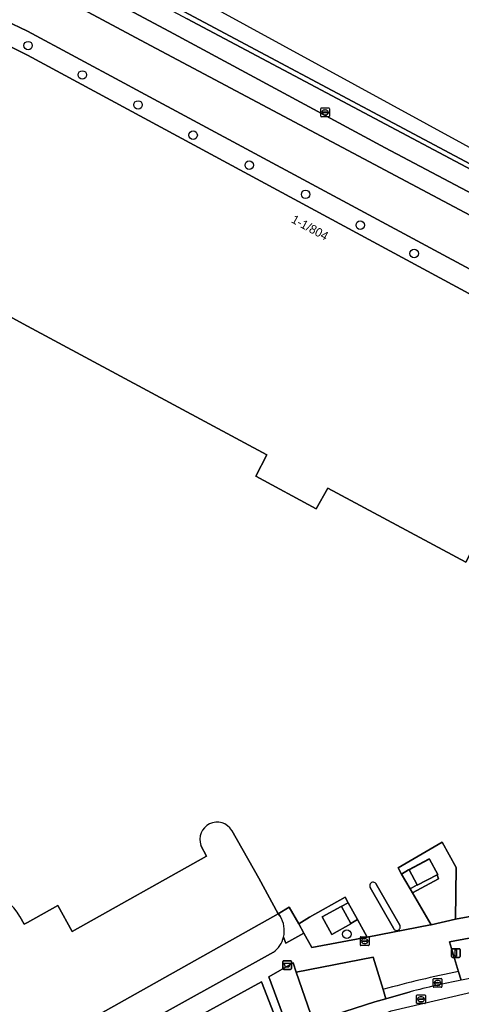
# Model space of a CAD drawing. Extents: x 159262 to 160143, y 383399 to 384319.
# Drawn here: x 159999.1 to 160049.8, y 383753.3 to 383866.4 of the extents above; entities that cross this region are included whole.
import ezdxf

# ---------------------------------------------------------------- set-up
doc = ezdxf.new("R2010")
doc.units = 0
for name, color, linetype in [('IMGEO_Afvalbak', 7, 'Continuous'), ('IMGEO_Berm_gesloten', 7, 'Continuous'), ('IMGEO_Boom', 7, 'Continuous'), ('IMGEO_Erf', 7, 'Continuous'), ('IMGEO_Fietspad_gesloten', 7, 'Continuous'), ('IMGEO_Groenvoorziening', 7, 'Continuous'), ('IMGEO_Kolk', 7, 'Continuous'), ('IMGEO_Lage_trafo', 7, 'Continuous'), ('IMGEO_Lichtmast', 7, 'Continuous'), ('IMGEO_Pand', 7, 'Continuous'), ('IMGEO_Pand_nummerreeks', 7, 'Continuous'), ('IMGEO_Parkeervlak_open', 7, 'Continuous'), ('IMGEO_Rijbaan_lokaal_gesloten', 7, 'Continuous'), ('IMGEO_Rioolput', 7, 'Continuous'), ('IMGEO_Voetpad_onverhard', 7, 'Continuous'), ('IMGEO_Voetpad_open', 7, 'Continuous')]:
    doc.layers.add(name, color=color, linetype=linetype)

msp = doc.modelspace()

# ---------------------------------------------------------------- linework, layer by layer
at = {"layer": 'IMGEO_Afvalbak'}
for p, q in [((160029.32, 383757.41), (160029.32, 383758.21)), ((160029.32, 383758.21), (160029.32, 383757.41)), ((160029.42, 383758.31), (160030.21, 383758.31)), ((160030.21, 383758.31), (160029.42, 383758.31)), ((160030.31, 383758.21), (160030.31, 383757.41)), ((160030.31, 383757.41), (160030.31, 383758.21)), ((160030.21, 383757.31), (160029.42, 383757.31)), ((160029.42, 383757.31), (160030.21, 383757.31))]:
    msp.add_line(p, q, dxfattribs=at)
msp.add_lwpolyline([(160029.46, 383758.03), (160030.17, 383758.03), (160030.02, 383757.56), (160029.61, 383757.56), (160029.46, 383758.03)], dxfattribs=at)
for centre, start, end in [((160029.42, 383758.21), 90, 180), ((160029.42, 383758.21), 90, 180), ((160030.21, 383758.21), 0, 90), ((160030.21, 383758.21), 360, 90), ((160029.42, 383757.41), 180, 270), ((160029.42, 383757.41), 180, 270), ((160030.21, 383757.41), 270, 0), ((160030.21, 383757.41), 270, 0)]:
    msp.add_arc(centre, 0.1, start, end, dxfattribs=at)
at = {"layer": 'IMGEO_Berm_gesloten'}
msp.add_lwpolyline([(159918.59, 383919.81), (159961.28, 383897), (159968.69, 383893.04), (160018.36, 383866.49), (160080.53, 383833.46), (160080.74, 383833.89), (159981.57, 383886.75), (159976.83, 383889.28)], dxfattribs=at)
at = {"layer": 'IMGEO_Boom'}
for centre in [(160000.08, 383863.42), (160006.31, 383860.05), (160012.7, 383856.61), (160019.02, 383853.13), (160025.47, 383849.69), (160031.94, 383846.34), (160038.21, 383842.79), (160044.4, 383839.55), (160036.67, 383761.36)]:
    msp.add_circle(centre, 0.489, dxfattribs=at)
at = {"layer": 'IMGEO_Erf'}
for points in [[(160059.65, 383769.61), (160059.1, 383772.65), (160054.73, 383772.65), (160054.73, 383772.95), (160054.15, 383773), (160054.45, 383777.99), (160054.74, 383782.8), (160052.48, 383783.01), (160053.43, 383787.92), (160055.71, 383799.6), (160057.92, 383798.99), (160058.58, 383801.32), (160050.95, 383805.29), (160050.31, 383804.09), (160034.47, 383812.6), (160033.14, 383810.21), (160026.23, 383813.96), (160027.49, 383816.42), (160000.02, 383831.2), (159992.6, 383835.2)], [(160023.48, 383773.27), (160026.56, 383767.79), (160028.78, 383763.7), (160030.05, 383764.45), (160031.15, 383762.56), (160032.4, 383763.31), (160036.46, 383765.6), (160036.82, 383764.96), (160037.9, 383763.06), (160039.02, 383761.03), (160046.26, 383762.43), (160046.33, 383762.45), (160044.19, 383766.09), (160043.93, 383766.55), (160042.95, 383768.25), (160042.55, 383768.97), (160047.6, 383771.91), (160049.23, 383769.01), (160049.13, 383763.07), (160056.27, 383764.37)], [(160020.56, 383770.33), (160019.91, 383771.54)], [(159999.12, 383763.37), (159999.65, 383762.5), (160000, 383762.7), (160003.48, 383764.65), (160005.15, 383761.68), (160020.56, 383770.33)], [(160042.01, 383762.04), (160039.35, 383766.72)], [(160040.05, 383767.09), (160042.74, 383762.39)]]:
    msp.add_lwpolyline(points, dxfattribs=at)
for centre, radius, start, end in [((160021.78, 383772.24), 1.99, 31.1501, 200.4441), ((160039.69, 383766.93), 0.4, 23.4886, 211.9549), ((159994.53, 383760.99), 5.18, 27.444, 133.522), ((160042.39, 383762.18), 0.406, 201.2941, 29.9981)]:
    msp.add_arc(centre, radius, start, end, dxfattribs=at)
at = {"layer": 'IMGEO_Fietspad_gesloten'}
for points in [[(159896.82, 383934.32), (159893.73, 383935.93), (159892.54, 383933.73), (159890.78, 383934.66), (159879.57, 383940.64), (159878.49, 383938.61), (159961, 383894.56), (159966.3, 383891.73), (160016.32, 383865.03), (160041.05, 383851.68), (160089.35, 383826.13)], [(160089.21, 383828.94), (160080.53, 383833.46), (160018.36, 383866.49)]]:
    msp.add_lwpolyline(points, dxfattribs=at)
at = {"layer": 'IMGEO_Groenvoorziening'}
for points in [[(160013.57, 383863.75), (159997.1, 383872.57), (159994.59, 383867.87), (159997.45, 383866.31), (160000, 383865.1), (160011.11, 383859.11), (160012.51, 383858.36), (160065.36, 383829.9), (160066.69, 383829.19), (160076.7, 383823.82), (160077.15, 383823.18), (160076.02, 383821.25), (160075.79, 383820.82), (160077.91, 383819.68), (160080.61, 383823.12), (160082.68, 383826.22), (160082.91, 383826.85), (160067.94, 383834.83)], [(160049.23, 383769.01), (160047.6, 383771.91), (160042.55, 383768.97), (160042.95, 383768.25), (160043.75, 383768.74), (160046.12, 383770), (160046.13, 383769.97), (160046.15, 383769.98), (160047.1, 383768.22), (160047.03, 383768.18), (160047.2, 383767.73), (160044.19, 383766.09), (160046.33, 383762.45), (160049.13, 383763.07)], [(160033.85, 383763.36), (160036.01, 383764.53), (160036, 383764.55), (160036.82, 383764.96), (160036.46, 383765.6), (160032.4, 383763.31), (160031.15, 383762.56), (160031.74, 383761.49), (160032.67, 383759.81), (160039.02, 383761.03), (160037.9, 383763.06), (160037.12, 383762.57), (160037.14, 383762.53), (160034.93, 383761.34)], [(160039.88, 383753.6), (160041.14, 383753.95), (160040.82, 383755), (160039.7, 383758.71), (160030.87, 383756.98), (160032.85, 383751.24), (160033.04, 383751.31), (160033.1, 383751.33), (160033.49, 383751.47), (160035.26, 383752.11)]]:
    msp.add_lwpolyline(points, close=True, dxfattribs=at)
for points in [[(160029, 383763.42), (160028.78, 383763.7), (160007.73, 383751.86), (160007.88, 383751.56)], [(160056.35, 383759.21), (160056.19, 383759.42), (160055.82, 383761.85), (160048.46, 383760.47), (160049.5, 383757.05), (160049.81, 383756.06)], [(160011.49, 383750), (160028.25, 383759.29)], [(160030.87, 383756.98), (160030.51, 383758.05), (160027.7, 383756.47), (160029.29, 383752.2), (160029.23, 383751.91)], [(160030.33, 383750.3), (160030.39, 383750.31), (160030.41, 383750.32), (160032.85, 383751.24), (160030.87, 383756.98)], [(160026.88, 383755.88), (160019.77, 383751.96), (160019.95, 383751.6), (160021.1, 383749.24)], [(160028.28, 383752.25), (160026.88, 383755.88)]]:
    msp.add_lwpolyline(points, dxfattribs=at)
for centre, radius, start, end in [((160026.41, 383761.76), 3.08, 346.2558, 32.6688), ((160026.41, 383761.76), 3.08, 306.703, 346.3127), ((160059.81, 383703.54), 53.47, 99.9103, 100.7871)]:
    msp.add_arc(centre, radius, start, end, dxfattribs=at)
at = {"layer": 'IMGEO_Kolk'}
for p, q in [((160046.59, 383755.34), (160046.59, 383756.19)), ((160046.66, 383756.27), (160047.51, 383756.27)), ((160046.84, 383755.76), (160046.84, 383755.77)), ((160047.28, 383755.72), (160046.88, 383755.72)), ((160046.89, 383755.81), (160047.28, 383755.81)), ((160047.07, 383756.04), (160047.1, 383756.04)), ((160047.1, 383755.49), (160047.07, 383755.49)), ((160047.33, 383755.77), (160047.33, 383755.76)), ((160047.59, 383756.19), (160047.59, 383755.34)), ((160047.51, 383755.26), (160046.66, 383755.26))]:
    msp.add_line(p, q, dxfattribs=at)
for points in [[(160046.59, 383755.34), (160046.59, 383756.19)], [(160046.66, 383756.27), (160047.51, 383756.27)], [(160047.59, 383756.19), (160047.59, 383755.34)], [(160047.51, 383755.26), (160046.66, 383755.26)]]:
    msp.add_lwpolyline(points, dxfattribs=at)
for centre, radius, start, end in [((160046.66, 383756.19), 0.0765, 91.552, 178.448), ((160046.66, 383756.19), 0.0765, 91.552, 178.448), ((160046.88, 383755.77), 0.0403, 85.8775, 175.7526), ((160046.88, 383755.76), 0.0366, 178.938, 274.7102), ((160047.29, 383755.77), 0.0386, 1.7309, 96.639), ((160047.29, 383755.76), 0.043, 264.8664, 352.4533), ((160047.51, 383756.19), 0.0765, 1.552, 88.448), ((160047.51, 383756.19), 0.0765, 1.552, 88.448), ((160046.66, 383755.34), 0.0765, 181.552, 268.448), ((160046.66, 383755.34), 0.0765, 181.552, 268.448), ((160047.51, 383755.34), 0.0765, 271.552, 358.448), ((160047.51, 383755.34), 0.0765, 271.552, 358.448)]:
    msp.add_arc(centre, radius, start, end, dxfattribs=at)
for centre, major_axis, ratio, start_param, end_param in [((160047.07, 383755.76), (-0.387, 0.002), 0.722429, 4.712389, 7.853982), ((160047.1, 383755.76), (-0.39, 0.002), 0.717154, 1.570796, 4.712389)]:
    msp.add_ellipse(centre, major_axis=major_axis, ratio=ratio, start_param=start_param, end_param=end_param, dxfattribs=at)
at = {"layer": 'IMGEO_Lage_trafo'}
for points in [[(160046.15, 383769.98), (160046.13, 383769.97), (160043.81, 383768.73), (160044.73, 383767.02), (160044.76, 383766.97), (160047.03, 383768.18), (160047.1, 383768.22)], [(160036.01, 383764.53), (160033.85, 383763.36), (160034.93, 383761.34), (160037.14, 383762.53), (160037.12, 383762.57), (160036.06, 383764.55)]]:
    msp.add_lwpolyline(points, close=True, dxfattribs=at)
at = {"layer": 'IMGEO_Lichtmast'}
for p, q in [((160048.69, 383758.79), (160048.69, 383759.59)), ((160048.69, 383759.59), (160048.69, 383758.79)), ((160048.79, 383759.69), (160049.58, 383759.69)), ((160049.58, 383759.69), (160048.79, 383759.69)), ((160049.68, 383759.59), (160049.68, 383758.79)), ((160049.68, 383758.79), (160049.68, 383759.59)), ((160049.58, 383758.69), (160048.79, 383758.69)), ((160048.79, 383758.69), (160049.58, 383758.69))]:
    msp.add_line(p, q, dxfattribs=at)
msp.add_lwpolyline([(160049.11, 383759.57), (160049.26, 383759.57), (160049.26, 383758.82), (160049.11, 383758.82), (160049.11, 383759.57)], dxfattribs=at)
for centre, start, end in [((160048.79, 383759.59), 90, 180), ((160048.79, 383759.59), 90, 180), ((160048.79, 383758.79), 180, 270), ((160048.79, 383758.79), 180, 270), ((160049.58, 383759.59), 0, 90), ((160049.58, 383759.59), 360, 90), ((160049.58, 383758.79), 270, 0), ((160049.58, 383758.79), 270, 0)]:
    msp.add_arc(centre, 0.1, start, end, dxfattribs=at)
at = {"layer": 'IMGEO_Pand'}
for points in [[(160000, 383862.31), (159996.3, 383864.17)], [(160083.15, 383820.78), (160080.9, 383822.56), (160081.06, 383822.76), (160080.61, 383823.12), (160077.91, 383819.68), (160075.79, 383820.82), (160076.02, 383821.25), (160000, 383862.31)], [(159992.6, 383835.2), (160000.02, 383831.2), (160027.49, 383816.42), (160026.23, 383813.96), (160033.14, 383810.21), (160034.47, 383812.6), (160050.31, 383804.09), (160050.95, 383805.29), (160058.58, 383801.32), (160057.92, 383798.99), (160055.71, 383799.6), (160053.43, 383787.92), (160052.48, 383783.01), (160054.74, 383782.8), (160054.45, 383777.99), (160054.15, 383773), (160054.73, 383772.95), (160054.73, 383772.65), (160059.1, 383772.65), (160059.65, 383769.61)], [(160028.78, 383763.7), (160026.56, 383767.79), (160023.48, 383773.27)], [(160019.91, 383771.54), (160020.56, 383770.33), (160005.15, 383761.68), (160003.48, 383764.65), (160000, 383762.7), (159999.65, 383762.5), (159999.12, 383763.37)], [(159969.13, 383743.25), (159972.28, 383737.48), (159974.58, 383733.26), (159995.4, 383744.96), (160003.58, 383749.53), (160007.73, 383751.86), (160028.78, 383763.7)]]:
    msp.add_lwpolyline(points, dxfattribs=at)
for centre, radius, start, end in [((160021.78, 383772.24), 1.99, 31.1501, 200.4441), ((159994.53, 383760.99), 5.18, 27.444, 133.522)]:
    msp.add_arc(centre, radius, start, end, dxfattribs=at)
at = {"layer": 'IMGEO_Parkeervlak_open'}
msp.add_lwpolyline([(159976.83, 383889.28), (159981.57, 383886.75), (160080.74, 383833.89), (160081.35, 383833.89), (160081.48, 383833.93), (160082.63, 383834.29), (160021.05, 383867.95)], dxfattribs=at)
at = {"layer": 'IMGEO_Rijbaan_lokaal_gesloten'}
for points in [[(160039.42, 383751.53), (160041.76, 383752.55), (160053.78, 383755.35), (160053.52, 383756.78), (160050.61, 383756.21)], [(160043.94, 383754.75), (160041.14, 383753.95), (160039.88, 383753.6), (160035.26, 383752.11), (160035.92, 383750.35)]]:
    msp.add_lwpolyline(points, dxfattribs=at)
for centre, radius, start, end in [((160065.24, 383673.56), 83.93, 100.5969, 104.7006), ((160059.81, 383703.54), 53.47, 99.9103, 100.7871)]:
    msp.add_arc(centre, radius, start, end, dxfattribs=at)
at = {"layer": 'IMGEO_Rioolput'}
for p, q in [((160033.67, 383855.33), (160033.67, 383856.18)), ((160033.75, 383856.26), (160034.6, 383856.26)), ((160034.16, 383856.03), (160034.18, 383856.03)), ((160034.67, 383856.18), (160034.67, 383855.33)), ((160034.6, 383855.25), (160033.75, 383855.25)), ((160033.93, 383855.75), (160033.93, 383855.76)), ((160033.97, 383855.8), (160034.37, 383855.8)), ((160034.37, 383855.71), (160033.97, 383855.71)), ((160034.18, 383855.48), (160034.16, 383855.48)), ((160034.41, 383855.76), (160034.41, 383855.75)), ((160038.29, 383761.05), (160039.15, 383761.05)), ((160038.22, 383760.13), (160038.22, 383760.98)), ((160039.15, 383760.05), (160038.29, 383760.05)), ((160038.48, 383760.55), (160038.48, 383760.56)), ((160038.52, 383760.6), (160038.92, 383760.6)), ((160038.91, 383760.51), (160038.52, 383760.51)), ((160038.73, 383760.27), (160038.7, 383760.27)), ((160038.71, 383760.83), (160038.73, 383760.83)), ((160038.96, 383760.56), (160038.96, 383760.55)), ((160039.22, 383760.98), (160039.22, 383760.13)), ((160044.68, 383753.45), (160044.68, 383754.31)), ((160044.76, 383754.38), (160045.61, 383754.38)), ((160045.68, 383754.31), (160045.68, 383753.45)), ((160045.61, 383753.38), (160044.76, 383753.38)), ((160044.94, 383753.87), (160044.94, 383753.89)), ((160044.98, 383753.92), (160045.38, 383753.92)), ((160045.38, 383753.84), (160044.98, 383753.84)), ((160045.17, 383754.16), (160045.2, 383754.16)), ((160045.19, 383753.6), (160045.17, 383753.6)), ((160045.43, 383753.89), (160045.43, 383753.87))]:
    msp.add_line(p, q, dxfattribs=at)
for points in [[(160033.67, 383855.33), (160033.67, 383856.18)], [(160033.75, 383856.26), (160034.6, 383856.26)], [(160034.67, 383856.18), (160034.67, 383855.33)], [(160034.6, 383855.25), (160033.75, 383855.25)], [(160038.29, 383761.05), (160039.15, 383761.05)], [(160038.22, 383760.13), (160038.22, 383760.98)], [(160039.15, 383760.05), (160038.29, 383760.05)], [(160039.22, 383760.98), (160039.22, 383760.13)], [(160044.68, 383753.45), (160044.68, 383754.31)], [(160044.76, 383754.38), (160045.61, 383754.38)], [(160045.68, 383754.31), (160045.68, 383753.45)], [(160045.61, 383753.38), (160044.76, 383753.38)]]:
    msp.add_lwpolyline(points, dxfattribs=at)
for centre, radius, start, end in [((160033.75, 383856.18), 0.0765, 91.552, 178.448), ((160033.75, 383856.18), 0.0765, 91.552, 178.448), ((160034.6, 383856.18), 0.0765, 1.552, 88.448), ((160034.6, 383856.18), 0.0765, 1.552, 88.448), ((160033.75, 383855.33), 0.0765, 181.552, 268.448), ((160033.75, 383855.33), 0.0765, 181.552, 268.448), ((160033.97, 383855.76), 0.0403, 85.8775, 175.7526), ((160033.97, 383855.75), 0.0366, 178.938, 274.7102), ((160034.38, 383855.76), 0.0386, 1.7309, 96.639), ((160034.37, 383855.75), 0.043, 264.8664, 352.4533), ((160034.6, 383855.33), 0.0765, 271.552, 358.448), ((160034.6, 383855.33), 0.0765, 271.552, 358.448), ((160038.29, 383760.98), 0.0765, 91.552, 178.448), ((160038.29, 383760.98), 0.0765, 91.552, 178.448), ((160039.14, 383760.98), 0.0765, 1.552, 88.448), ((160039.14, 383760.98), 0.0765, 1.552, 88.448), ((160038.29, 383760.13), 0.0765, 181.552, 268.448), ((160038.29, 383760.13), 0.0765, 181.552, 268.448), ((160038.52, 383760.56), 0.0403, 85.8775, 175.7526), ((160038.51, 383760.55), 0.0366, 178.938, 274.7102), ((160038.92, 383760.55), 0.043, 264.8664, 352.4533), ((160038.92, 383760.56), 0.0386, 1.7309, 96.639), ((160039.14, 383760.13), 0.0765, 271.552, 358.448), ((160039.14, 383760.13), 0.0765, 271.552, 358.448), ((160044.76, 383754.31), 0.0765, 91.552, 178.448), ((160044.76, 383754.31), 0.0765, 91.552, 178.448), ((160045.61, 383754.31), 0.0765, 1.552, 88.448), ((160045.61, 383754.31), 0.0765, 1.552, 88.448), ((160044.76, 383753.46), 0.0765, 181.552, 268.448), ((160044.76, 383753.46), 0.0765, 181.552, 268.448), ((160044.98, 383753.88), 0.0403, 85.8775, 175.7526), ((160044.98, 383753.87), 0.0366, 178.938, 274.7102), ((160045.39, 383753.89), 0.0386, 1.7309, 96.639), ((160045.38, 383753.88), 0.043, 264.8664, 352.4533), ((160045.61, 383753.46), 0.0765, 271.552, 358.448), ((160045.61, 383753.46), 0.0765, 271.552, 358.448)]:
    msp.add_arc(centre, radius, start, end, dxfattribs=at)
for centre, major_axis, ratio, start_param, end_param in [((160034.16, 383855.75), (-0.387, 0.002), 0.722429, 4.712389, 7.853982), ((160034.18, 383855.75), (-0.39, 0.002), 0.717154, 1.570796, 4.712389), ((160038.71, 383760.55), (-0.387, 0.002), 0.722429, 4.712389, 7.853982), ((160038.73, 383760.55), (-0.39, 0.002), 0.717154, 1.570796, 4.712389), ((160045.17, 383753.88), (-0.387, 0.002), 0.722429, 4.712389, 7.853982), ((160045.19, 383753.88), (-0.39, 0.002), 0.717154, 1.570796, 4.712389)]:
    msp.add_ellipse(centre, major_axis=major_axis, ratio=ratio, start_param=start_param, end_param=end_param, dxfattribs=at)
at = {"layer": 'IMGEO_Voetpad_onverhard'}
msp.add_lwpolyline([(160012.51, 383858.36), (160011.11, 383859.11), (160000, 383865.1), (159997.45, 383866.31), (159996.3, 383864.17), (160000, 383862.31), (160076.02, 383821.25), (160077.15, 383823.18), (160076.7, 383823.82), (160066.69, 383829.19), (160065.36, 383829.9)], close=True, dxfattribs=at)
at = {"layer": 'IMGEO_Voetpad_open'}
for points in [[(159966.3, 383891.73), (159961, 383894.56), (159960.63, 383892.03), (159965.01, 383889.67), (159966.94, 383888.69), (159967.48, 383888.4), (159983.16, 383880.03), (159990.76, 383875.96), (159995.23, 383873.57), (159997.1, 383872.57), (160013.57, 383863.75), (160067.94, 383834.83), (160082.91, 383826.85), (160086.32, 383825.03)], [(160089.35, 383826.13), (160041.05, 383851.68), (160016.32, 383865.03), (159966.3, 383891.73)], [(160039.35, 383766.72), (160042.01, 383762.04)], [(160042.74, 383762.39), (160040.05, 383767.09)], [(160134.17, 383766.53), (160089.79, 383766.39), (160089.53, 383766.39), (160087.23, 383766.38), (160086.65, 383766.35), (160077.83, 383766.14), (160077.82, 383766.14), (160075.4, 383766.15), (160072.4, 383766.1), (160062.78, 383765.39), (160062.78, 383765.34), (160060.5, 383765.07), (160060.5, 383765.1), (160060.46, 383765.09), (160056.27, 383764.37), (160049.13, 383763.07), (160046.33, 383762.45), (160046.26, 383762.43), (160039.02, 383761.03), (160032.67, 383759.81), (160031.74, 383761.49), (160029.67, 383760.33), (160029.4, 383761.03)], [(160031.15, 383762.56), (160030.05, 383764.45), (160028.78, 383763.7), (160029, 383763.42)], [(160029.4, 383761.03), (160029.67, 383760.33), (160031.74, 383761.49), (160031.15, 383762.56)], [(160049.5, 383757.05), (160048.46, 383760.47), (160055.82, 383761.85), (160056.19, 383759.42), (160056.35, 383759.21)], [(160028.25, 383759.29), (160011.49, 383750), (159994.53, 383740.41), (159978.83, 383731.54), (159971.83, 383727.58), (159968.52, 383725.77), (159967.57, 383725.25), (159955.18, 383718.47), (159948.25, 383714.67), (159947, 383713.98), (159943.69, 383712.17), (159941.75, 383711.19), (159937.58, 383708.93), (159935.98, 383707.68), (159934.21, 383706.21), (159934.31, 383705.94), (159934.62, 383705.2)], [(160029.23, 383751.91), (160029.29, 383752.2), (160027.7, 383756.47), (160030.51, 383758.05), (160030.87, 383756.98), (160039.7, 383758.71), (160040.82, 383755)], [(160049.81, 383756.06), (160049.5, 383757.05)], [(160021.1, 383749.24), (160019.95, 383751.6), (160019.77, 383751.96), (160026.88, 383755.88), (160028.28, 383752.25)], [(160040.82, 383755), (160041.14, 383753.95), (160043.94, 383754.75)]]:
    msp.add_lwpolyline(points, dxfattribs=at)
for points in [[(160043.81, 383768.73), (160046.13, 383769.97), (160046.12, 383770), (160043.75, 383768.74), (160042.95, 383768.25), (160043.93, 383766.55), (160044.73, 383767.02)], [(160047.2, 383767.73), (160047.03, 383768.18), (160044.76, 383766.97), (160044.73, 383767.02), (160043.93, 383766.55), (160044.19, 383766.09)], [(160036.82, 383764.96), (160036, 383764.55), (160036.01, 383764.53), (160036.06, 383764.55), (160037.12, 383762.57), (160037.9, 383763.06)]]:
    msp.add_lwpolyline(points, close=True, dxfattribs=at)
for centre, radius, start, end in [((160039.69, 383766.93), 0.4, 23.4886, 211.9549), ((160026.41, 383761.76), 3.08, 346.2558, 32.6688), ((160042.39, 383762.18), 0.406, 201.2941, 29.9981), ((160026.41, 383761.76), 3.08, 306.703, 346.3127), ((160071.24, 383645.64), 113.52, 101.0407, 105.5462), ((160071.24, 383645.64), 113.52, 101.0407, 105.5462), ((160065.24, 383673.56), 83.93, 100.5969, 104.7006)]:
    msp.add_arc(centre, radius, start, end, dxfattribs=at)

# ---------------------------------------------------------------- texts
at = {"layer": 'IMGEO_Pand_nummerreeks'}
msp.add_text('1-1/804', height=1, rotation=331.6271, dxfattribs=at).set_placement((160030.2, 383843.16))

doc.saveas('drawing.dxf')
